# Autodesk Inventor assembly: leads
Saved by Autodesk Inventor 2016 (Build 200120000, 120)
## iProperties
Created: 2018-05
Part Number: leads
Document SubType Name: Assembly
Designer: Administrator
Title: leads
Author: Administrator
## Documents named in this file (6)
- c:\worker\convert-fusion-mar-2018\tmp\job-1\16\output\files\8c58ff39-88bb-4352-afd9-60265520bae5\leads.iam
- c:\worker\convert-fusion-mar-2018\tmp\job-1\16\output\files\8c58ff39-88bb-4352-afd9-60265520bae5\Component12.ipt
- c:\worker\convert-fusion-mar-2018\tmp\job-1\16\output\files\8c58ff39-88bb-4352-afd9-60265520bae5\Component13.ipt
- c:\worker\convert-fusion-mar-2018\tmp\job-1\16\output\files\8c58ff39-88bb-4352-afd9-60265520bae5\Component14.ipt
- c:\worker\convert-fusion-mar-2018\tmp\job-1\16\output\files\8c58ff39-88bb-4352-afd9-60265520bae5\Component15.ipt
- c:\worker\convert-fusion-mar-2018\tmp\job-1\16\output\files\8c58ff39-88bb-4352-afd9-60265520bae5\Component16.ipt
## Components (10 placed, 5 different names)
1. Component12:1
2. Component13:1
3. Component14:1
4. Component12:2
5. Component12:3
6. Component12:4
7. Component12:5
8. Component15:1
9. Component16:1
10. Component14:2
